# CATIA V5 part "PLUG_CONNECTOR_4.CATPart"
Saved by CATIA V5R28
Part number: PLUG_CONNECTOR_4
Revision: ---
Publications: "MasterKeywayAxis", "InsertFrontFace", "InsertRearFace", "Logical Termination.1", "Logical Pin.1", "CCP", "Face_generated(CCP)", "Face_generated(CCP).1", "BCP", "BCPRPoint_generated(BCP)", "BCPPlane_generated(BCP)", "BaCP", "Face_generated(BaCP)", "Face_generated(BaCP).1", "CaCP", "Face_generated(CaCP)", "Axis_generated(CaCP)", "Face_generated(CaCP).1", "Axis_generated(BaCP)", "Axis_generated(CCP)"
Bounding box of the stored display mesh (mm): x 0 to 36.297, y -14.795 to 14.795, z -14.795 to 14.795
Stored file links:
  C:\Users\ajc8720\Documents\BOEING_WORK\0001-2CES\004-AP242\Boeing-Generic_Harness_R3\PLUG_CONNECTOR_4.CATPart
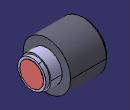
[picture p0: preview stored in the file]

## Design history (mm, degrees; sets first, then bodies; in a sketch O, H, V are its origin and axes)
Parameters
  PartNumber = "PLUG_CONNECTOR_4"
AxisSystem1 "MasterKeywayAxis": origin (0, 0, 0), X (1, 0, 0), Y (0, 1, 0), Z (0, 0, 1)
Set1 "EGF"
  Set2 "CCP"
    Point1 "CCPRPoint": (14.0208 {= deleted_ShoulderFront}, 0, 0)
    Plane1 "CCPCPlane": type OffsetPt, RefPlane yz-plane, RefPoint Point1
  Set3 "BaCP"
    Point2 "BaCPRPoint": (36.0934 {= deleted_ShellLength}, 0, 0)
    Plane2 "BaCPCPlane": type OffsetPt, RefPlane yz-plane, RefPoint Point2
  Set4 "BCP"
    Plane3 "BCPPlane": type Offset, RefPlane face of Pad6, Offset 0, reversed
    Point3 "BCPRPoint": type OnPlane, Support Plane3, H 0, V 0, Direction (0, 1, 0)
  Set5 "CaCP"
    Point4 "CaCPRPoint": (14.0208 {= deleted_ShoulderFront}, 0, 0)
    Plane4 "CaCPCPlane": type OffsetPt, RefPlane yz-plane, RefPoint Point4
Body1 "CouplingRing" (main body)
  Sketch1 on yz-plane, origin (0, 0, 0), H (0, 1, 0), V (0, 0, 1)
    circle A1 centre (0, 0) radius 14.7955
    radius A1 = 14.7955
  Pad1 "CouplingRing": profile Sketch1, direction (1, 0, 0), length 26.7716 {= deleted_CouplingRingFront + deleted_CouplingRingLength}, opposite side length -2.54 {= -( deleted_CouplingRingFront )}
  Sketch2 on zx-plane, origin (0, 0, 0), H (-1, 0, 0), V (0, 0, 1)
    line L1 (-4.5212, 14.7955) -> (-2.54, 14.7955)
    line L2 (-2.54, 14.7955) -> (-2.54, 12.827)
    line L3 (-2.54, 12.827) -> (-4.5212, 12.827)
    line L4 (-4.5212, 12.827) -> (-4.5212, 14.7955)
    distance H L3 = 12.827
    distance H L1 = 14.7955
    distance V L2 = 2.54
    length L1 = 1.9812
    horizontal: L1 H, L3 H
    vertical: L2 V, L4 V
  Groove1 "CouplingRingRelief": profile Sketch2, axis Sketch2.H, angle 360
  Sketch3 on face of Pad1, origin (2.54, 0, 0), H (0, -1, 0), V (0, 0, 1)
    point P1 (0, 0)
    reference intersected line E1 through (0, 0) direction (-1, 0) from xy-plane
    reference intersected line E2 through (0, 0) direction (0, -1) from zx-plane
    coincidence: P1 E1, P1 E2
  Hole1 "CouplingRingID": placed by Sketch3, at (2.54, 0, 0) direction (1, 0, 0), diameter 22.733 {= deleted_CouplingRingFrontID}, depth 22.0472 {= deleted_CouplingRingThreadLength}, counterbore diameter 22.733 {= deleted_CouplingRingFrontID}, counterbore depth 1.9812 {= deleted_CouplingRingFrontIDLength}
  Sketch4 on face of Hole1, origin (24.5872, 0, 0), H (0, 1, 0), V (0, 0, -1)
    point P1 (0, 0)
    reference intersected line E1 through (0, 0) direction (0, 1) from zx-plane
    reference intersected line E2 through (0, 0) direction (1, 0) from xy-plane
    coincidence: P1 E1, P1 E2
  Hole2 "CouplingRingThruHole": placed by Sketch4, at (24.5872, 0, 0) direction (1, 0, 0), diameter 19.05 {= deleted_CouplingRingThruDia}, through (limit type 6)
Body2 "Shell"
  Sketch5 on yz-plane, origin (0, 0, 0), H (0, 1, 0), V (0, 0, 1)
    circle A1 centre (0, 0) radius 8.8392
    radius A1 = 8.8392
  Pad2 "ShellFront": profile Sketch5, direction (1, 0, 0), length 14.0208 {= deleted_ShoulderFront}
  Sketch6 on yz-plane, origin (0, 0, 0), H (0, 1, 0), V (0, 0, 1)
    circle A1 centre (0, 0) radius 9.525
    radius A1 = 9.525
  Pad3 "ShellBack": profile Sketch6, direction (1, 0, 0), length 36.0934 {= deleted_ShellLength}, opposite side length -14.0208 {= -( deleted_ShoulderFront )}
  Sketch7 on zx-plane, origin (0, 0, 0), H (-1, 0, 0), V (0, 0, 1)
    line L1 (-36.0934, 9.525) -> (-28.321, 9.525)
    line L2 (-33.7312, 9.525) -> (-33.7312, 8.7249)
    line L3 (-33.7312, 8.7249) -> (-36.0934, 8.7249)
    line L4 (-36.0934, 8.7249) -> (-36.0934, 9.525)
    line L5 (-28.321, 9.525) -> (-28.321, 9.525)
    line L6 (-28.321, 9.525) -> (-33.7312, 9.525)
    distance V L4 = 36.0934
    length L1 = 7.7724
    length L3 = 2.3622
    distance H L3 = 8.7249
    distance H L6 = 9.525
    distance L1 H = 9.525
    horizontal: L1 H, L3 H, L6 H
    vertical: L2 V, L4 V, L5 V
  Groove2 "AccyTeethThread": profile Sketch7, axis Sketch7.H, angle 360
  Sketch8 on yz-plane, origin (0, 0, 0), H (0, 1, 0), V (0, 0, 1)
    point P1 (-1.0668, 0)
    line L1 (-1.0668, 0) -> (1.0668, 0)
    line L2 (1.0668, 0) -> (1.0668, 9.398)
    line L3 (1.0668, 9.398) -> (-1.0668, 9.398)
    line L4 (-1.0668, 9.398) -> (-1.0668, 0)
    length L3 = 2.1336
    distance H L3 = 9.398
    coincidence: P1 H
    horizontal: L1 H, L3 H
    vertical: L2 V, L4 V
    symmetry: L2 L4 V
  Pad4 "MasterKeyway": profile Sketch8, direction (1, 0, 0), length 14.0208 {= deleted_ShoulderFront}, opposite side length -4.572 {= - ( deleted_MasterKeyFront )}
  Sketch9 on face of Pad2, origin (0, 0, 0), H (0, -1, 0), V (0, 0, 1)
    point P1 (0, 0)
    reference intersected line E1 through (0, 0) direction (0, -1) from zx-plane
    reference intersected line E2 through (0, 0) direction (-1, 0) from xy-plane
    coincidence: P1 E1, P1 E2
  Hole3 "FrontShellID": placed by Sketch9, at (0, 0, 0) direction (1, 0, 0), diameter 15.1892 {= deleted_ShellFrontID}, depth 26.7716 {= deleted_ShellLength - deleted_ShellRearIDLength}
  Sketch10 on face of Pad3, origin (36.0934, 0, 0), H (0, 1, 0), V (0, 0, 1)
    point P1 (0, 0)
    reference intersected line E1 through (0, 0) direction (0, 1) from zx-plane
    reference intersected line E2 through (0, 0) direction (-1, 0) from xy-plane
    coincidence: P1 E1, P1 E2
  Hole4 "RearShellID": placed by Sketch10, at (36.0934, 0, 0) direction (-1, 0, 0), diameter 14.732 {= deleted_ShellRearID}, depth 9.3218 {= deleted_ShellRearIDLength}
Body3 "Insert"
  Sketch11 on yz-plane, origin (0, 0, 0), H (0, 1, 0), V (0, 0, 1)
    circle A1 centre (0, 0) radius 7.2263
    radius A1 = 7.2263
  Pad5 "InsertOD": profile Sketch11, direction (1, 0, 0), length 23.5966 {= deleted_InsertFront + deleted_InsertLength - deleted_GrommetLength}, opposite side length -2.54 {= -( deleted_InsertFront )}
  Sketch12 on yz-plane, origin (0, 0, 0), H (0, 1, 0), V (0, 0, 1)
    circle A1 centre (0, 0) radius 7.366
    radius A1 = 7.366
  Pad6 "GrommetOD": profile Sketch12, direction (1, 0, 0), length 36.2966 {= deleted_InsertFront + deleted_InsertLength}, opposite side length -23.5966 {= -( deleted_InsertFront + deleted_InsertLength - deleted_GrommetLength )}
Body4 "CCP"
  Sketch13 on face of Pad3, origin (14.0208, 0, 0), H (0, 1, 0), V (0, 0, 1)
    arc A1 centre (0, 0) radius 1.016 from (-0.672, 0.762) to (0.672, 0.762) ccw
    line L1 (-0.672, 0.762) -> (0.672, 0.762)
    distance L1 H = 0.762
    radius A1 = 1.016
  Pad7: profile Sketch13, direction (1, 0, 0), length 0.508
Body5 "CaCP"
  Sketch14 "Sketch" on start face of Pad3, origin (14.0208, 0, 0), H (0, 1, 0), V (0, 0, 1)
    line L1 (-0.672, 0.762) -> (0.672, 0.762)
    point P1 (-0.672, 0.762)
    point P2 (0.672, 0.762)
    arc A1 centre (0, 0) radius 1.016 from (-1.016, 0) to (1.016, 0) ccw
    point P3 (0, 0)
    point P4 (-1.016, 0)
    point P5 (1.016, 0)
    reference projected point E1 (0, 0) from Point4
    arc A2 centre (0, 0) radius 1.016 from (1.016, 0) to (0.672, 0.762) ccw
    point P6 (0, 0)
    point P7 (1.016, 0)
    point P8 (0.672, 0.762)
    arc A3 centre (0, 0) radius 1.016 from (-0.672, 0.762) to (-1.016, 0) ccw
    point P9 (0, 0)
    point P10 (-0.672, 0.762)
    point P11 (-1.016, 0)
    reference projected point E2 (0, 0) from Point4
    reference projected point E3 (0, 0) from Point4
    length L1 = 1.344
    radius A1 = 1.016
    radius A3 = 1.016
    radius A2 = 1.016
    distance L1 P5 = 0.762
    distance P4 L1 = 0.762
    distance P7 L1 = 0.762
    distance P11 L1 = 0.762
    coincidence: P3 E1, P6 E2, P9 E3, P8 P2, P10 P1
    horizontal: L1 H
  Pad8: profile Sketch14, direction (1, 0, 0), length 0.508, opposite side up to start face of Pad3
Body6 "BaCP"
  Sketch15 on face of Pad3, origin (36.0934, 0, 0), H (0, 1, 0), V (0, 0, 1)
    arc A1 centre (0, 0) radius 1.016 from (-0.672, 0.762) to (0.672, 0.762) ccw
    line L1 (-0.672, 0.762) -> (0.672, 0.762)
    distance L1 H = 0.762
    radius A1 = 1.016
  Sketch16 on face of Pad3, origin (36.0934, 0, 0), H (0, 1, 0), V (0, 0, 1)
    circle A1 centre (0, 0) radius 1.27
    radius A1 = 1.27
  Pad9: profile Sketch16, direction (1, 0, 0), length 0.254, opposite side length 0.254
  Pocket1: profile Sketch15, direction (1, 0, 0), through (limit type 6)
Relations
  Sketch7.distance(H L3) = Shell\Sketch.21\Offset.45\Offset ShellRearOD / 2 (deactivated)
